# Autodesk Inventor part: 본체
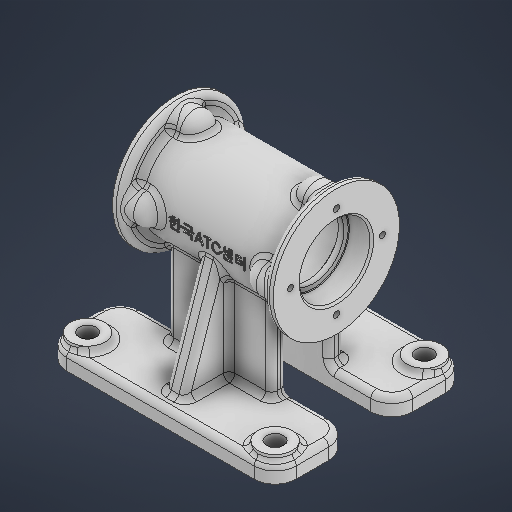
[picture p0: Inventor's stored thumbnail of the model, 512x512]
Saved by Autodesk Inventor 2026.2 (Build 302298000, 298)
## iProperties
Created: 2026-06
Part Number: 본체
Material: 알루미늄 6061
Document SubType Name: Modeling
Designer: sec7
Density: 2.7 g/cm^3
Appearance: 기본값
Mass: 612.594 g
Surface Area: 669.191 cm^2
Volume: 226.887 cm^3
Author: sec7
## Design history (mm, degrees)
sketch "스케치1"
  geometry: C1 r 25 at (0, 0); 1 further point
  constraints: 1 centre point, 1 coincident
  dimensions: "d0" = 50 diameter of C1
extrude "돌출1" new body sketch "스케치1" stored distance "d1" = 84; taper "d2" = 0 deg
sketch "스케치2"
  geometry: C1 r 33 at (0, 0); 1 further point
  constraints: 1 centre point, 1 coincident
  dimensions: "d3" = 66 diameter of C1
extrude "돌출2" join sketch "스케치2" distance "d4" = 5; taper "d5" = 0 deg
sketch "스케치3"
  geometry: C1 r 8 at (0, 24); 1 further point
  constraints: 1 centre point, 1 vertical alignment
  dimensions: "d6" = 16 diameter of C1; "d7" = 24 distance of point (0, 0) C1.centre
extrude "돌출3" join sketch "스케치3" distance "d8" = 13; taper "d9" = 0 deg
fillet "모깎기1" dims "d10" = 8
sketch "스케치4"
  geometry: 2 further points
  constraints: 1 vertical alignment
  dimensions: "d11" = 24 distance of point (0, 0) point (0, 24)
hole "구멍1" sketch "스케치4" at (0, 24) diameter "d12" = 3.242; stored, may be unused: countersink angle "d16" = 90 deg, drill point angle "d18" = 120 deg; dims "d13" = 8, "d14" = 4, "d15" = 2, "d17" = 10
node "작업 평면1"
sketch "스케치5"
  geometry: L1 (60, 11)-(-60, 11); L2 (-60, 11)-(-60, 50); L3 (-60, 50)-(60, 50); L4 (60, 50)-(60, 11); L5 (60, -50)-(-60, -50); L6 (-60, -50)-(-60, -11); L7 (-60, -11)-(60, -11); L8 (60, -11)-(60, -50); 3 further points
  constraints: 16 end point, 4 parallel, 2 horizontal, 2 midpoint, 2 perpendicular, 2 vertical alignment, 1 collinear
  dimensions: "d23" = 39 distance of L7.end L5.start; "d24" = 120 distance of L5.start L5.end; "d25" = 120 distance of L1.start L1.end; "d26" = 50 distance from line of point (0, 0) L5; "d27" = 100 distance between parallel lines of L3 L5
extrude "돌출4" join sketch "스케치5" distance "d28" = 9; taper "d29" = 0 deg
sketch "스케치6"
  geometry: L1 (60, -11)-(-60, -11) reference; L2 (-27, -11)-(27, -11); L3 (27, -11)-(27, -19); L4 (27, -19)-(-27, -19); L5 (-27, -19)-(-27, -11); L6 (-60, 11)-(60, 11) reference; L7 (-27, 11)-(27, 11); L8 (27, 11)-(27, 19); L9 (27, 19)-(-27, 19); L10 (-27, 19)-(-27, 11); 5 further points
  constraints: 16 end point, 4 parallel, 2 horizontal, 2 midpoint, 2 perpendicular, 2 point on line, 2 vertical alignment
  dimensions: "d30" = 54 distance of L3.end L4.end; "d31" = 8 distance of L2.end L3.end; "d32" = 54 distance of L8.end L9.end; "d33" = 8 distance of L9.end L7.start
extrude "돌출5" join sketch "스케치6" stored distance "d34" = 9; taper "d35" = 0 deg
sketch "스케치7"
  geometry: L1 (-61, 11)-(-61, 50) reference; L2 (-61, 43)-(-6.346, 24.181); L3 (-61, 19)-(-16.248, 19) reference; A1 r 25 centre (0, 0) between (-6.346, 24.181) and (-16.248, 19) reference; 1 further point
  constraints: 2 end point, 1 point on circle, 1 point on line
  dimensions: "d36" = 7 distance of L1.end L2.start; "d37" = 19 deg angle of L3 L2
feature "리브1" sketch "스케치7" dims "d38" = 1, "d39" = 10, "d40" = 0, "d41" = 0, "d42" = 1, "d43" = 1
fillet "모깎기4" dims "d46" = 3
fillet "모깎기5" dims "d47" = 3
sketch "스케치8"
  geometry: C1 r 9 at (-49, -39); C2 r 9 at (49, -39); C3 r 9 at (-49, 39); C4 r 9 at (49, 39); 1 further point
  constraints: 4 centre point, 2 horizontal alignment, 2 vertical alignment
  dimensions: "d51" = 18 diameter of C1; "d52" = 18 diameter of C2; "d53" = 18 diameter of C3; "d54" = 18 diameter of C4; "d55" = 78 distance of C1.centre C3.centre; "d56" = 39 vertical distance of point (0, 0) C3.centre; "d57" = 98 distance of C4.centre C3.centre; "d58" = 49 horizontal distance of point (0, 0) C3.centre
extrude "돌출6" join sketch "스케치8" distance "d59" = 3; taper "d60" = 0 deg
fillet "모깎기7" dims "d49" = 3
fillet "모깎기8" dims "d50" = 3
fillet "모깎기9" dims "d61" = 11
sketch "스케치9"
  geometry: L1 (-42, 0)-(42, 0); L2 (42, -33)-(42, 33) reference; L3 (-42, 25)-(-42, -25) reference; L4 (-42, 18.5)-(-30.3, 18.5); L5 (-30, 18.2)-(-30, 16); L6 (-30, 16)-(-27, 16); L7 (-27, 16)-(-27, 17); L8 (-24, 20)-(24, 20); L9 (27, 17)-(27, 16); L10 (27, 16)-(30, 16); L11 (30, 16)-(30, 18.2); L12 (30.3, 18.5)-(42, 18.5); A1 r 0.3 centre (-30.3, 18.2) between (-30, 18.2) and (-30.3, 18.5); A2 r 0.3 centre (30.3, 18.2) between (30.3, 18.5) and (30, 18.2); A3 r 3 centre (24, 17) between (27, 17) and (24, 20); A4 r 3 centre (-24, 17) between (-24, 20) and (-27, 17); 3 further points
  constraints: 20 end point, 10 point on line, 8 point on circle, 8 tangent, 6 perpendicular, 4 centre point, 2 equal radius, 2 midpoint, 1 horizontal
  dimensions: "d63" = 40 diameter of L8 L1; "d64" = 37 diameter of L12 L1; "d65" = 32 diameter of L6 L1; "d66" = 12 distance of L4.start point (-30, 18.5); "d67" = 54 distance between parallel lines of L9 L7; "d68" = 27 distance from line of point (0, 0) L7; "d69" = 12 distance of point (30, 18.5) L12.end; "d70" = 0.3 radius of A1; "d71" = 3 radius of A3
revolve "회전1" sketch "스케치9" stored, may be unused: angle "d72" = 90 deg
fillet "모깎기11" dims "d73" = 3
fillet "모깎기13" dims "d75" = 3
fillet "모깎기14" dims "d76" = 3
chamfer "모따기1" distance "d77" = 1; stored, may be unused: second distance "d78" = 2, angle "d79" = 45 deg
sketch "스케치10"
  geometry: C1 r 9 at (0, 0) reference; C2 r 9 at (98, 0) reference; C3 r 9 at (0, -78) reference; C4 r 9 at (98, -78) reference; 5 further points
  constraints: 4 coincident
hole "구멍2" sketch "스케치10" at (0, 0), (98, 0), (0, -78), (98, -78) diameter "d80" = 9; stored, may be unused: countersink angle "d84" = 90 deg, drill point angle "d86" = 120 deg; dims "d81" = 8, "d82" = 4, "d83" = 2, "d85" = 10
fillet "모깎기15" dims "d87" = 3
sketch "스케치11" dims "d0" = 50
  geometry: L1 (0, 0)-(98, 0) reference; 3 further points
  constraints: 1 midpoint, 1 vertical alignment, 1 other
  dimensions: "d88" = 70 distance from line of L1 point (49, 70)
fillet "모깎기16" dims "d89" = 3
feature "엠보싱1" dims "d0" = 50, "d90" = 0.5, "d91" = 0
sketch "스케치12"
  geometry: L1 (-58, -11)-(-26.833, -11) reference; L2 (-26.833, 11)-(-58, 11) reference; L3 (-50, 11)-(-50, -11); L4 (-70, -22)-(-70, -11) reference; 1 further point
  constraints: 2 end point, 2 point on line, 1 perpendicular
  dimensions: "d92" = 20 distance between parallel lines of L4 L3
feature "리브2" sketch "스케치12" dims "d93" = 1, "d94" = 10, "d95" = 0, "d96" = 0, "d97" = 1, "d98" = 1
fillet "모깎기17" dims "d99" = 3
fillet "모깎기18" dims "d100" = 3
node "솔리드1"
pattern_circular "원형 패턴1" dims "d20" = 360 deg
mirror "미러1"
mirror "미러2"
feature "A9D066F2-1C7D-4E18-AEED-F7BC21143FA4" dims "d80" = 9, "d81" = 8, "d82" = 4, "d83" = 2, "d84" = 90 deg, "d85" = 10, "d86" = 120 deg
